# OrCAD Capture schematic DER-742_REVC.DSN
size Custom
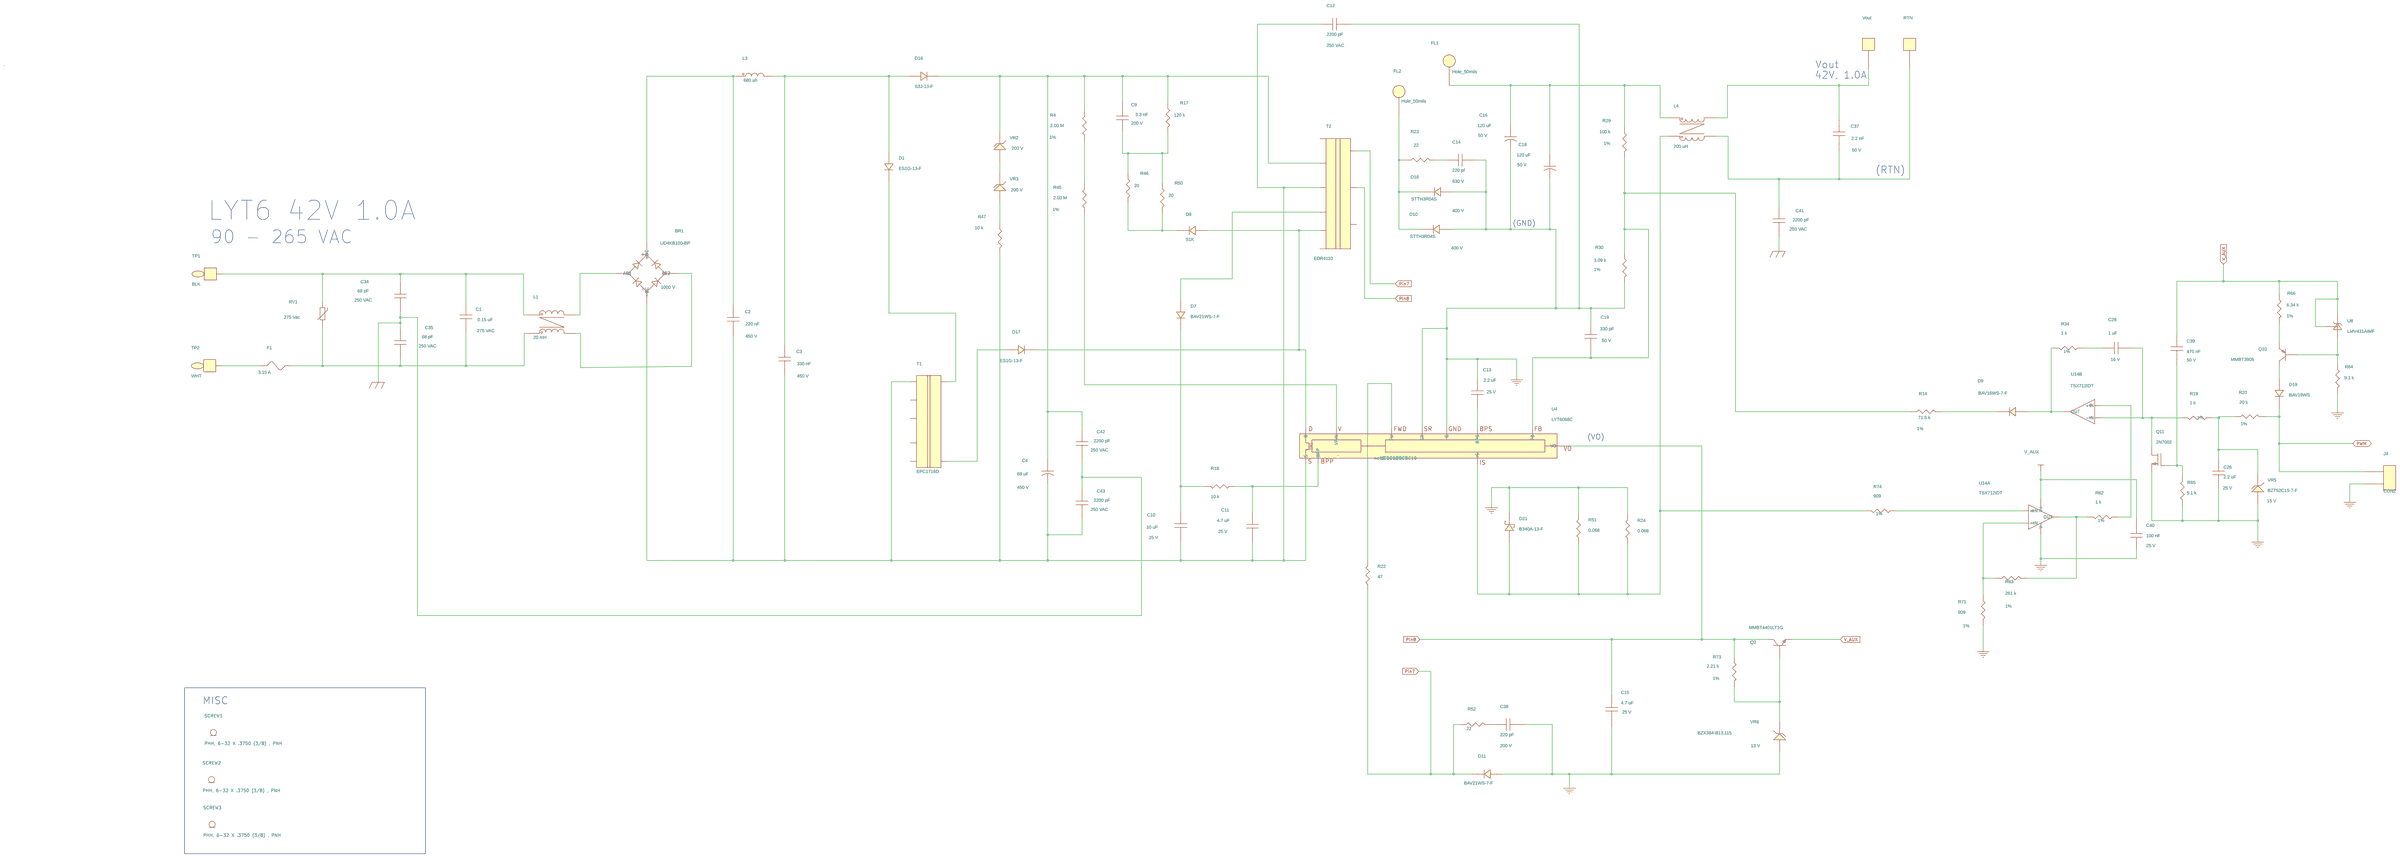
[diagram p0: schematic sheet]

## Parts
BR1  UD4KB100-BP  [pidaxbridgeD3K]
C1  0.15 uF  [pinpxcaprad13x7LS10mmD040]
C2  220 nF  [pi_np_cap_rad470x220ls400d40]
C3  330 nF  [pi_np_caprad512x299ls394d040]
C4  68 uF  [pipolcapclyd500ls200040]
C9  3.3 nF  [pismc0805]
C10  10 uF  [pismc1206]
C11  4.7 uF  [pismc0805]
C12  2200 pF  [pinpcaprad9p0D10p0LS030]
C13  2.2 uF  [pismc1206]
C14  220 pf  [pismc1206]
C15  4.7 uF  [pismc1206]
C16  120 uF  [pipolcapclyd320ls140030]
C18  120 uF  [pipolcapclyd320ls140030]
C19  330 pF  [pismc0603]
C26  2.2 uF  [pismc0805]
C28  1 uF  [pismc0603]
C34  68 pF  [pinpycaprad470x210ls380040]
C35  68 pF  [pinpycaprad470x210ls380040]
C37  2.2 nF  [pismc0805]
C38  220 pF  [pismc0805]
C39  470 nF  [pismc0603]
C40  100 nF  [pismc0603]
C41  2200 pF  [pinpcaprad9p0D10p0LS030]
C42  2200 pF  [pinpcaprad9p0D10p0LS030]
C43  2200 pF  [pinpcaprad9p0D10p0LS030]
D1  ES1G-13-F  [pismdo214ac12]
D7  BAV21WS-7-F  [pismsod323]
D8  S1K  [pismdo214ac12]
D9  BAV16WS-7-F  [pismsod323]
D10  STTH3R04S  [pismdo214ab12]
D11  BAV21WS-7-F  [pismsod323]
D16  S3J-13-F  [pismdo214ab12]
D17  ES1G-13-F  [pismdo214ac12]
D18  STTH3R04S  [pismdo214ab12]
D19  BAV19WS  [pismsod323]
D21  B340A-13-F  [pismdo214ac12]
F1  3.15 A  [pi_rst_microfuse]
FL1  Hole_50mils  [pi_hole_50mil]
FL2  Hole_50mils  [pi_hole_50mil]
J4  CON2  [pimolex2kkheader]
L1  20 mH  [pi_toroid_DER742CMC]
L3  680 uh  [pi_choke_RL5480-4_d2]
L4  200 uH  [pi_toroid_DER742CMCL4]
Q2  MMBT4401LT1G  [pismsot23123_1]
Q10  MMBT3906  [pismsot23123_1]
Q11  2N7002  [pismsot23123_1]
R4  2.00 M  [pismr1206]
R14  71.5 k  [pismr0603]
R17  120 k  [pismr1206]
R18  10 k  [pismr1206]
R19  1 k  [pismr0603]
R20  20 k  [pismr0603]
R22  47  [pismr1206]
R23  22  [pismr1206]
R24  0.068  [pismr1206]
R29  100 k  [pismr0805]
R30  3.09 k  [pismr0603]
R34  1 k  [pismr0603]
R45  2.00 M  [pismr1206]
R46  20  [pismr1206]
R47  10 k  [pismr0805]
R50  20  [pismr1206]
R51  0.068  [pismr1206]
R52  22  [pismr0805]
R62  1 k  [pismr0603]
R63  261 k  [pismr0603]
R64  9.1 k  [pismr0805]
R65  5.1 k  [pismr0603]
R66  6.34 k  [pismr0603]
R71  909  [pismr0603]
R73  2.21 k  [pismr0805]
R74  909  [pismr0603]
RTN  PCB Terminal 18 AWG  [pi_hole_18awg]
RV1  275 Vac  [pidisc350x160ls210x140040]
SCREW1  PHH, 6-32 X .3750 (3/8) , PNH
SCREW2  PHH, 6-32 X .3750 (3/8) , PNH
SCREW3  PHH, 6-32 X .3750 (3/8) , PNH
T1  EPC1716D  [pi_bobbin_epc1716D_7p]
T2  EDR4110  [pi_bobbin_EDR4110_9p_6x3]
TP1  BLK  [pitpkeystone125x125]
TP2  WHT  [pitpkeystone125x125]
U4  LYT6068C  [pi_ic_insop_24d]
U8  LMV431AIMF  [pismsot23132]
U14  TSX712IDT  [pismso8]  (sections A,B)
Vout  PCB Terminal 18 AWG  [pi_hole_18awg]
VR2  1SMA200Z  [pismdo214ac12]
VR3  1SMA200Z  [pismdo214ac12]
VR5  BZT52C15-7-F  [pi_sm_sod-123_12]
VR6  BZX384-B13,115  [pismsod323]

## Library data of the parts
BR1 = DISCRETE_BRIDGE_+~~-: ALT_SYMBOLS: pidaxbridgeD3K_horz; Disp_Voltage: 1000 V; FPLIST: pidaxbridgeD3K,pidaxbridgeD3K_horz; Part Number: 15-01213-00
C1 = CAP_NP: ALT_SYMBOLS: pinpxcaprad13x7LS10mmD040H; Disp_Voltage: 275 VAC; FPLIST: pinpxcaprad13x7LS10mmD040,pinpxcaprad13x7LS10mmD040H; Part Number: 20-09139-00; Voltage: 275 VAC
C2 = CAP_NP: ALT_SYMBOLS: pi_np_cap_rad470x220ls400d40_h; Disp_Voltage: 450 V; FPLIST: pi_np_cap_rad470x220ls400d40,pi_np_cap_rad470x220ls400d40_h; Part Number: 20-08691-00; Voltage: 450 V
C3 = CAP_NP: ALT_SYMBOLS: pi_np_caprad512x299ls394d040_h; Disp_Voltage: 450 V; FPLIST: pi_np_caprad512x299ls394d040,pi_np_caprad512x299ls394d040_h; Part Number: 20-00973-00; Voltage: 450 V
C4 = CAP_POL: ALT_SYMBOLS: pipolcapclyd500ls2000401650lh; Disp_Voltage: 450 V; FPLIST: pipolcapclyd500ls200040,pipolcapclyd500ls2000401650lh; Part Number: 20-09155-00; Voltage: 450 V
C9 = CAP_NP: Disp_Voltage: 200 V; Part Number: 20-00956-00; Voltage: 200 V
C10 = CAP_NP: Disp_Voltage: 25 V; Part Number: 20-08608-00; Voltage: 25 V
C11 = CAP_NP: Disp_Voltage: 25 V; Part Number: 20-09022-00; Voltage: 25 V
C12 C41-C43 = CAP_NP: Disp_Voltage: 250 VAC; Part Number: 20-09158-00; Voltage: 250 VAC
C13 = CAP_NP: Disp_Voltage: 25 V; Part Number: 20-01034-00; Voltage: 25 V
C14 = CAP_NP: Disp_Voltage: 630 V; Part Number: 20-01036-00; Voltage: 630 V
C15 = CAP_NP: Disp_Voltage: 25 V; Part Number: 20-00572-00; Voltage: 25 V
C16 C18 = CAP_POL: ALT_SYMBOLS: pipolcapclyd320ls140030430h; COMPGROUP: 3; Disp_Voltage: 50 V; FPLIST: pipolcapclyd320ls140030,pipolcapclyd320ls140030430h; Part Number: 20-09170-00; Voltage: 50 V
C19 = CAP_NP: Disp_Voltage: 50 V; Part Number: 20-08676-00; Voltage: 50 V
C26 = CAP_NP: Disp_Voltage: 25 V; Part Number: 20-08603-00; ROOM: 4; Voltage: 25 V
C28 = CAP_NP: Disp_Voltage: 16 V; Part Number: 20-01020-00; ROOM: 4; Voltage: 16 V
C34 C35 = CAP_NP: Disp_Voltage: 250 VAC; Part Number: 20-00557-00; Voltage: 250 VAC
C37 = CAP_NP: Disp_Voltage: 50 V; Part Number: 20-00961-00; Voltage: 50 V
C38 = CAP_NP: Disp_Voltage: 200 V; Part Number: 20-09094-00; Voltage: 200 V
C39 = CAP_NP: Disp_Voltage: 50 V; Part Number: 20-08678-00; ROOM: 4; Voltage: 50 V
C40 = CAP_NP: Disp_Voltage: 25 V; Part Number: 20-00528-00; ROOM: 4; Voltage: 25 V
D1 D17 = DIODE: COMPGROUP: 1; Part Number: 15-01074-00
D7 D11 = DIODE: Part Number: 15-00385-00
D8 = DIODE: Part Number: 15-01296-00
D9 = DIODE: Part Number: 15-00850-00
D10 D18 = DIODE: Disp_Voltage: 400 V; Part Number: 15-01274-00
D16 = DIODE: COMPGROUP: 1; Part Number: 15-01061-00
D19 = DIODE: Part Number: 15-00658-00
D21 = DIODE_SCHOTTKY: Part Number: 15-01172-00
F1 = FUSE: ALT_SYMBOLS: pirstmicrofusehoz; FPLIST: pi_rst_microfuse,pirstmicrofusehoz; Part Number: 40-00071-00; Voltage: 250 V
FL1 FL2 = FlyingLead: Part Number: 35-00283-00
J4 = CON2: Part Number: 35-00077-00
L1 = TORRID_4P_13_24: Part Number: 32-00372-00
L3 = INDUCTOR_dot2: ALT_SYMBOLS: pi_choke_RL5480-4H_d2; FPLIST: pi_choke_RL5480-4_d2,pi_choke_RL5480-4H_d2; Part Number: 30-00336-00
L4 = TORRID_4P_13_24: Part Number: 32-00373-00
Q2 = NPN_BEC: Part Number: 55-00152-00
Q10 = PNP_BEC: Part Number: 55-00049-00
Q11 = FET_N_GSD: Part Number: 50-00103-00
R4 R45 = R: Disp_Tol: 1%; Part Number: 05-03156-00
R14 = R: Disp_Tol: 1%; Part Number: 05-03266-00; ROOM: 1
R17 = R: Part Number: 05-01402-00
R18 = R: Part Number: 05-01376-00
R19 R34 R62 = R: Disp_Tol: 1%; Part Number: 05-01078-00; ROOM: 1
R20 = R: Disp_Tol: 1%; Part Number: 05-03213-00; ROOM: 1
R22 = R: Part Number: 05-01320-00
R23 = R: Part Number: 05-01312-00
R24 R51 = R: Disp_Tol: 1%; Part Number: 05-06499-00
R29 = R: Disp_Tol: 1%; Part Number: 05-00780-00
R30 = R: Disp_Tol: 1%; Part Number: 05-01125-00
R46 R50 = R: Part Number: 05-01311-00
R47 = R: Part Number: 05-01543-00
R52 = R: Part Number: 05-01479-00
R63 = R: Disp_Tol: 1%; Part Number: 05-01214-00; ROOM: 1
R64 = R: Part Number: 05-01542-00
R65 = R: Part Number: 05-01705-00; ROOM: 1
R66 = R: Disp_Tol: 1%; Part Number: 05-01155-00
R71 R74 = R: Disp_Tol: 1%; Part Number: 05-01074-00; ROOM: 1
R73 = R: Disp_Tol: 1%; Part Number: 05-03341-00
RTN Vout = TERM_1Pin: Part Number: 35-00007-00
RV1 = VARISTOR: ALT_SYMBOLS: pi_disc_354x220_ls220x10_040_h; FPLIST: pidisc350x160ls210x140040,pi_disc_354x220_ls220x10_040_h; Part Number: 85-00015-00
SCREW1-SCREW3 = SCR_6-32: Part Number: 75-00009-00
T1 = BEFD18_7P: Part Number: 25-01026-00
T2 = BEQ20_9P: Part Number: 25-01139-00
TP1 = TESTPOINT: Part Number: 35-00042-00
TP2 = TESTPOINT: Part Number: 35-00044-00
U4 = LYT6: Part Number: 10-01081-00
U8 = TL431_SOT-23_RCA: Part Number: 45-00019-00
U14 = TSX712IDT: Part Number: 45-00514-00
VR2 VR3 = DIODE_ZENER: Disp_Voltage: 200 V; Part Number: 15-00671-00
VR5 = DIODE_ZENER: Disp_Voltage: 15 V; Part Number: 15-00923-00
VR6 = DIODE_ZENER: Disp_Voltage: 13 V; Part Number: 15-00819-00

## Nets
GND: C12.2 C13.1 C14.2 C15.2 C16.2 C18.2 C19.1 C26.2 C38.2 C40.1 D10.2 D11.2 D18.2 D21.1 J4.2 Q11.2(S) R24.2 R30.2 R51.2 R64.1 R65.1 R71.2 U4.2(G) U4.5(SR) U14.4(V-) VR5.2 VR6.2
GND_EARTH: C34.2 C35.1 C41.2 C42.2 C43.1
NC8: U4.8(NC8)
NC9: U4.9(NC9)
NC10: U4.10(NC10)
NC11: U4.11(NC11)
NC12: U4.12(NC12)
NC15: U4.15(nc15)
Pin7: D11.1 R22.1 R52.1 T2.7
Pin8: C15.1 Q2.3(COLLECTOR) R73.1 T2.8 U4.6(VO)
PWM: D19.1 J4.1 R20.2
V_AUX: C39.1 C40.2 Q2.2(EMITTER) R66.1 U8.1(VREF) U8.2(C) U14.8(V+)
N10967118: C10.1 D7.1 R18.1
N10967192: D8.1 R46.2 R50.2
N10967272: D8.2 D17.1 T2.2 U4.24(D)
N10967292: C4.1 C9.2 C42.1 D16.1 R4.2 R17.1 T2.5 VR2.1
N10967352: C11.1 R18.2 U4.14(BPP)
N10967360: C19.2 R14.2 R29.2 R30.1 U4.3(FB)
N10967588: C16.1 C18.1 FL1.1 L4.1 R29.1
N10967616: D10.1 D18.1 FL2.1 R23.2
N10968210: C14.1 R23.1
N10968562: BR1.4(-DC) C2.2 C3.2 C4.2 C10.2 C11.2 C12.1 C43.2 R47.2 T1.1 T2.4 U4.16(S)
N10970513: C1.2 C35.2 F1.2 L1.1 RV1.1
N10971255: BR1.3(AC2) L1.3
N10975943: C9.1 R17.2 R46.1 R50.1
N11207739: C1.1 C34.1 L1.2 RV1.2 TP1.1
N11231482: R22.2 U4.7(FW)
N11317958: R45.1 U4.13(VPIN)
N11319179: C13.2 U4.4(BPS)
N11446006: D1.1 T1.7
N11450999: C3.1 D1.2 D16.2 L3.1
N11459929: BR1.1(+DC) C2.1 L3.2
N11465077: F1.1 TP2.1
N11478809: VR2.2 VR3.1
N11478836: R47.1 VR3.2
N11497112: C38.1 R52.2
N11921550: Q10.2(EMITTER) R66.2
N11921594: Q10.1(BASE) R64.2 U8.3(A)
N11921660: C39.2 Q11.1(G) R65.2
N11921664: D19.2 Q10.3(COLLECTOR)
N11921668: D9.2 R34.2 U14.7(OUT)
N11921676: C28.1 R34.1
N11921680: C28.2 Q11.3(D) R19.2 U14.6(-IN)
N11921778: R62.1 U14.5(+IN)
N11921790: D9.1 R14.1
N11921854: C26.1 R19.1 R20.1 VR5.1
N11922118: R62.2 R63.2 U14.1(OUT)
N11922154: R63.1 R71.1 U14.2(-IN)
N11926287: C37.1 L4.3 Vout.1
N11926309: C37.2 C41.1 L4.4 RTN.1
N11929315: R4.1 R45.2
N11931425: D7.2 T2.3
N11945881: D21.2 L4.2 R24.1 R51.1 R74.2 U4.1(IS)
N11960452: R74.1 U14.3(+IN)
N12237167: D17.2 T1.6
N12249644: Q2.1(BASE) R73.2 VR6.1
N12296601: BR1.2(AC1) L1.4

Not connected (* = marked no-connect by the designer): T1 2 3 4 5; T2 1 6 9

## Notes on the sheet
- Vout
- 42V, 1.0A
- (RTN)
- LYT6 42V 1.0A
- (GND)
- 90 - 265 VAC
- (VO)
- MISC
